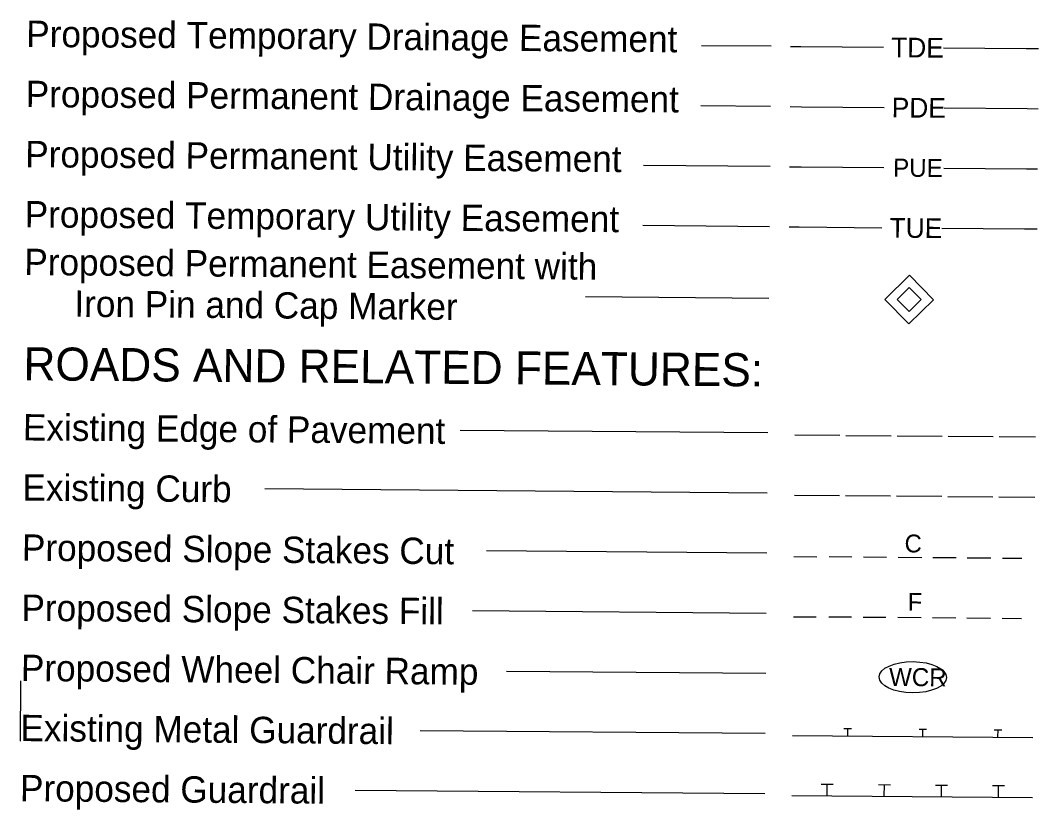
# Model space of a CAD drawing. Extents: x 1379453 to 1387082, y 594364 to 596664.
# Drawn here: x 1384837 to 1385514, y 594991 to 595516 of the extents above; entities that cross this region are included whole.
import ezdxf

# ---------------------------------------------------------------- set-up
doc = ezdxf.new("R2010")
doc.units = 0
for name, color, linetype in [('Default', 7, 'Continuous'), ('Prop ROW Permanent Easement CELL', 7, 'Continuous'), ('Sheet Symbology CELL', 7, 'Continuous')]:
    doc.layers.add(name, color=color, linetype=linetype)

msp = doc.modelspace()

# ---------------------------------------------------------------- linework, layer by layer
at = {"layer": 'Default'}
msp.add_line((1384836.81, 595036.39), (1384837.12, 595076.36), dxfattribs=at)
at = {"layer": 'Prop ROW Permanent Easement CELL'}
msp.add_line((1385428.08, 595330.04), (1385428.08, 595330.04), dxfattribs=at)
for points in [[(1385428.22, 595346.14), (1385444.18, 595329.9), (1385427.95, 595313.93), (1385411.98, 595330.17)], [(1385428.15, 595338.08), (1385436.13, 595329.97), (1385428.01, 595321.98), (1385420.03, 595330.1)]]:
    msp.add_lwpolyline(points, close=True, dxfattribs=at)
at = {"layer": 'Sheet Symbology CELL'}
for p, q in [((1385336.17, 595498.45), (1385289.88, 595498.84)), ((1385349.2, 595498.35), (1385355.9, 595498.29)), ((1385355.9, 595498.29), (1385410.9, 595497.83)), ((1385450.89, 595497.49), (1385505.89, 595497.03)), ((1385505.89, 595497.03), (1385514.19, 595496.96)), ((1385335.84, 595458.46), (1385289.54, 595458.84)), ((1385348.86, 595458.35), (1385356.46, 595458.28)), ((1385356.46, 595458.28), (1385411.46, 595457.82)), ((1385451.46, 595457.49), (1385506.46, 595457.03)), ((1385506.46, 595457.03), (1385513.86, 595456.96)), ((1385335.5, 595418.46), (1385251.23, 595419.16)), ((1385348.53, 595418.35), (1385356.2, 595418.28)), ((1385356.2, 595418.28), (1385411.2, 595417.82)), ((1385451.2, 595417.49), (1385506.2, 595417.03)), ((1385506.2, 595417.03), (1385513.52, 595416.97)), ((1385335.17, 595378.46), (1385250.9, 595379.17)), ((1385348.19, 595378.35), (1385354.89, 595378.29)), ((1385354.89, 595378.29), (1385409.89, 595377.83)), ((1385449.89, 595377.5), (1385504.89, 595377.04)), ((1385504.89, 595377.04), (1385513.19, 595376.97)), ((1385334.77, 595330.82), (1385212.75, 595331.84)), ((1385334.02, 595241.3), (1385129.33, 595243.02)), ((1385352.03, 595240), (1385382.03, 595239.75)), ((1385386.03, 595239.72), (1385416.03, 595239.47)), ((1385420.03, 595239.43), (1385450.03, 595239.18)), ((1385454.03, 595239.15), (1385484.03, 595238.9)), ((1385488.03, 595238.86), (1385512.03, 595238.66)), ((1385333.68, 595201.3), (1384999.4, 595204.1)), ((1385351.7, 595200), (1385381.7, 595199.75)), ((1385385.7, 595199.72), (1385415.7, 595199.47)), ((1385419.7, 595199.43), (1385449.7, 595199.18)), ((1385453.7, 595199.15), (1385483.69, 595198.9)), ((1385487.69, 595198.86), (1385511.69, 595198.66)), ((1385333.35, 595161.31), (1385146.98, 595162.87)), ((1385351.36, 595159.05), (1385366.56, 595158.93)), ((1385389.95, 595158.73), (1385374.86, 595158.86)), ((1385412.95, 595158.54), (1385397.75, 595158.67)), ((1385436.45, 595158.34), (1385420.85, 595158.47)), ((1385459.35, 595158.15), (1385443.85, 595158.28)), ((1385482.45, 595157.96), (1385466.75, 595158.09)), ((1385503.05, 595157.78), (1385490.25, 595157.89)), ((1385333.01, 595121.31), (1385137.55, 595122.94)), ((1385351.02, 595119.06), (1385366.22, 595118.93)), ((1385389.62, 595118.73), (1385374.52, 595118.86)), ((1385412.62, 595118.54), (1385397.42, 595118.67)), ((1385436.12, 595118.34), (1385420.52, 595118.47)), ((1385459.02, 595118.15), (1385443.52, 595118.28)), ((1385482.12, 595117.96), (1385466.42, 595118.09)), ((1385502.72, 595117.79), (1385489.92, 595117.89)), ((1385332.68, 595081.31), (1385160.16, 595082.75)), ((1385332.37, 595041.33), (1385102.7, 595043.26)), ((1385350.38, 595040.03), (1385510.38, 595038.69)), ((1385384.7, 595044.75), (1385389.7, 595044.7)), ((1385387.16, 595039.73), (1385387.2, 595044.73)), ((1385434.7, 595044.33), (1385439.7, 595044.29)), ((1385437.16, 595039.31), (1385437.2, 595044.31)), ((1385484.7, 595043.91), (1385489.7, 595043.87)), ((1385487.15, 595038.89), (1385487.2, 595043.89)), ((1385369.56, 595007.77), (1385377.56, 595007.7)), ((1385373.5, 594999.84), (1385373.56, 595007.74)), ((1385407.56, 595007.45), (1385415.56, 595007.39)), ((1385411.5, 594999.52), (1385411.56, 595007.42)), ((1385445.56, 595007.14), (1385453.56, 595007.07)), ((1385449.5, 594999.2), (1385449.56, 595007.1)), ((1385483.56, 595006.82), (1385491.56, 595006.75)), ((1385487.49, 594998.88), (1385487.56, 595006.78)), ((1385332.03, 595001.34), (1385059.57, 595003.62)), ((1385510.04, 594998.69), (1385350.05, 595000.04))]:
    msp.add_line(p, q, dxfattribs=at)
msp.add_ellipse((1385430.53, 595078.85), major_axis=(22.43, -0.19), ratio=0.462467, dxfattribs=at)

# ---------------------------------------------------------------- texts
for s, height, p in [('Proposed Temporary Drainage Easement', 17.5, (1384840.65, 595498.08)), ('TDE', 13.1, (1385416.04, 595491.19)), ('Proposed Permanent Drainage Easement', 17.5, (1384840.32, 595458.08)), ('PDE', 13.1, (1385416.41, 595451.18)), ('Proposed Permanent Utility Easement', 17.5, (1384839.98, 595418.08)), ('PUE', 12, (1385417.35, 595411.77)), ('Proposed Temporary Utility Easement', 17.5, (1384839.65, 595378.09)), ('TUE', 13.1, (1385415, 595371.19)), ('Proposed Permanent Easement with', 17.5, (1384839.38, 595346.36)), ('Iron Pin and Cap Marker', 17.5, (1384872.67, 595318.58)), ('ROADS AND RELATED FEATURES:', 22, (1384838.8, 595276.35)), ('Existing Edge of Pavement', 17.5, (1384838.46, 595236.35)), ('Existing Curb', 17.5, (1384838.13, 595196.36)), ('Proposed Slope Stakes Cut', 17.5, (1384837.79, 595156.36)), ('C', 11.85, (1385424.98, 595161.91)), ('F', 11.85, (1385427.06, 595123.14)), ('Proposed Slope Stakes Fill', 17.5, (1384837.46, 595116.36)), ('Proposed Wheel Chair Ramp', 17.5, (1384837.12, 595076.36)), ('WCR', 12, (1385414.64, 595073.07)), ('Existing Metal Guardrail', 17.5, (1384836.81, 595036.39)), ('Proposed Guardrail', 17.5, (1384836.5, 594996.41))]:
    msp.add_text(s, height=height, rotation=359.52002, dxfattribs=at).set_placement(p)

doc.saveas('drawing.dxf')
